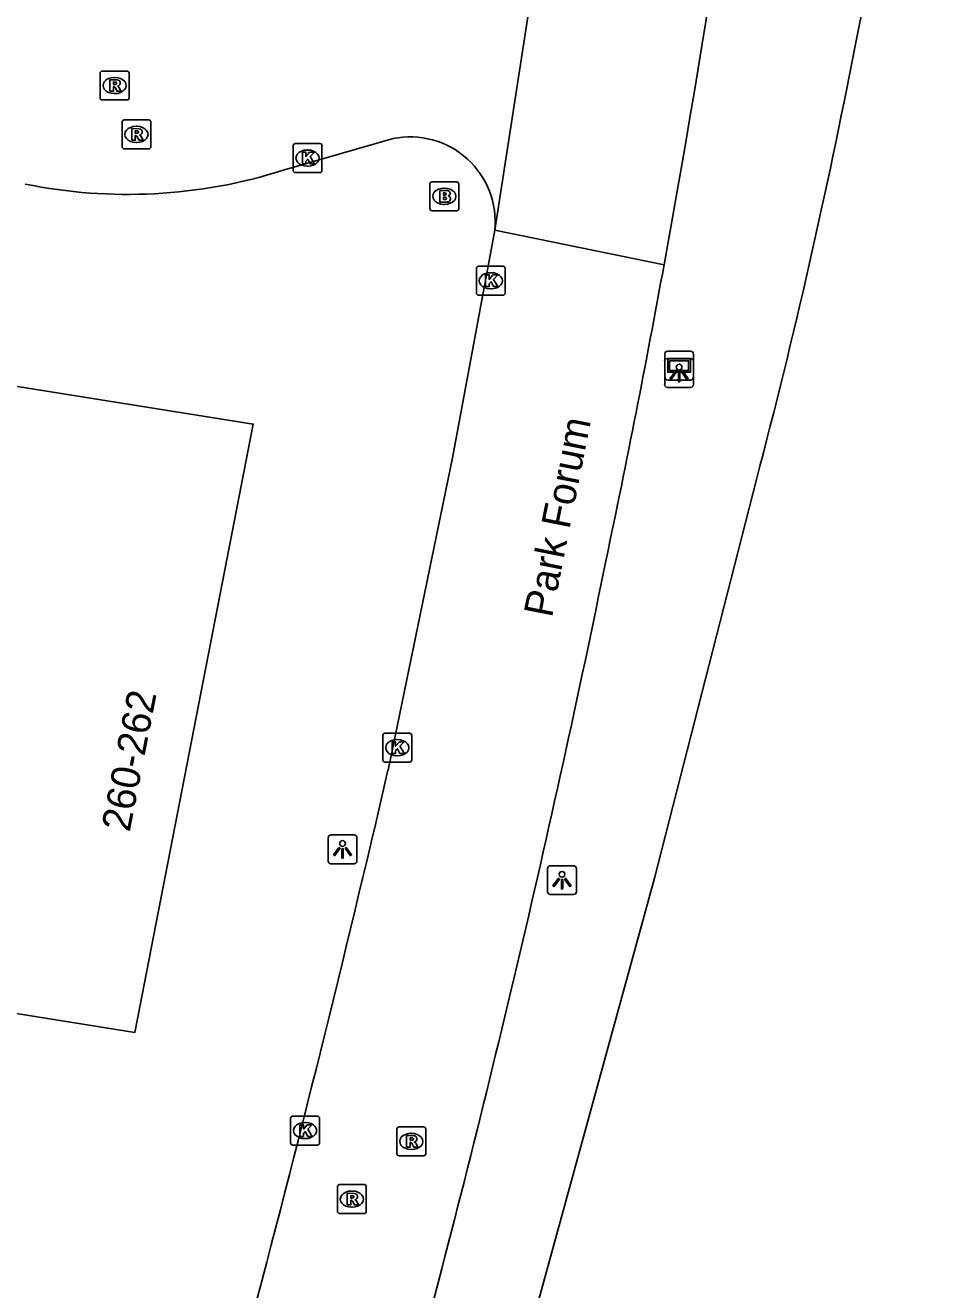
# Model space of a CAD drawing. Extents: x 154324 to 155743, y 382939 to 384183.
# Drawn here: x 155360.3 to 155392.1, y 383255.99 to 383299.76 of the extents above; entities that cross this region are included whole.
import ezdxf

# ---------------------------------------------------------------- set-up
doc = ezdxf.new("R2010")
doc.units = 0
for name, color, linetype in [('IMGEO_Brandkraan', 7, 'Continuous'), ('IMGEO_Fietspad_gesloten', 7, 'Continuous'), ('IMGEO_Kolk', 7, 'Continuous'), ('IMGEO_Lichtpunt', 7, 'Continuous'), ('IMGEO_Openbare_ruimte_label', 7, 'Continuous'), ('IMGEO_Pand', 7, 'Continuous'), ('IMGEO_Pand_nummerreeks', 7, 'Continuous'), ('IMGEO_Rijbaan_lokaal_gesloten', 7, 'Continuous'), ('IMGEO_Rijbaan_lokaal_open', 7, 'Continuous'), ('IMGEO_Rioolput', 7, 'Continuous'), ('IMGEO_Verklikker', 7, 'Continuous')]:
    doc.layers.add(name, color=color, linetype=linetype)

msp = doc.modelspace()

# ---------------------------------------------------------------- linework, layer by layer
at = {"layer": 'IMGEO_Brandkraan'}
for p, q in [((155374.307, 383293.413), (155374.307, 383294.265)), ((155374.382, 383294.339), (155375.234, 383294.339)), ((155374.795, 383294.119), (155374.82, 383294.119)), ((155375.308, 383294.265), (155375.308, 383293.413)), ((155375.234, 383293.339), (155374.382, 383293.339)), ((155374.818, 383293.559), (155374.793, 383293.559))]:
    msp.add_line(p, q, dxfattribs=at)
for points in [[(155374.307, 383293.413), (155374.307, 383294.265)], [(155374.382, 383294.339), (155375.234, 383294.339)], [(155375.308, 383294.265), (155375.308, 383293.413)], [(155374.655, 383294.039), (155374.655, 383293.639), (155374.868, 383293.639)], [(155374.886, 383294.039), (155374.655, 383294.039)], [(155374.834, 383293.958), (155374.78, 383293.958), (155374.78, 383293.882)], [(155374.78, 383293.882), (155374.833, 383293.882)], [(155374.842, 383293.806), (155374.78, 383293.806), (155374.78, 383293.725)], [(155374.78, 383293.725), (155374.842, 383293.725)], [(155375.234, 383293.339), (155374.382, 383293.339)]]:
    msp.add_lwpolyline(points, dxfattribs=at)
for centre, radius, start, end in [((155374.384, 383294.263), 0.0765, 91.552, 178.448), ((155374.384, 383294.263), 0.0765, 91.552, 178.448), ((155375.232, 383294.263), 0.0765, 1.552, 88.448), ((155375.232, 383294.263), 0.0765, 1.552, 88.448), ((155374.835, 383293.92), 0.0379, 267.8285, 90.9355), ((155374.843, 383293.765), 0.0404, 269.8759, 90.5077), ((155374.89, 383293.894), 0.145, 59.4692, 91.5367), ((155374.915, 383293.941), 0.0922, 285.5137, 58.1501), ((155374.92, 383293.749), 0.105, 301.3115, 78.989), ((155374.384, 383293.415), 0.0765, 181.552, 268.448), ((155374.384, 383293.415), 0.0765, 181.552, 268.448), ((155374.874, 383293.89), 0.251, 268.6676, 293.5347), ((155375.232, 383293.415), 0.0765, 271.552, 358.448), ((155375.232, 383293.415), 0.0765, 271.552, 358.448)]:
    msp.add_arc(centre, radius, start, end, dxfattribs=at)
for centre, major_axis, ratio, start_param, end_param in [((155374.794, 383293.839), (-0.387, 0.002), 0.722429, 4.712389, 7.853982), ((155374.819, 383293.839), (-0.39, 0.002), 0.717154, 1.570796, 4.712389)]:
    msp.add_ellipse(centre, major_axis=major_axis, ratio=ratio, start_param=start_param, end_param=end_param, dxfattribs=at)
at = {"layer": 'IMGEO_Fietspad_gesloten'}
for points in [[(155392.104, 383314.484), (155389.025, 383298.986)], [(155385.619, 383284.035), (155382.092, 383270.232), (155378.211, 383256.107)]]:
    msp.add_lwpolyline(points, dxfattribs=at)
for centre, radius, start, end in [((155162.148, 383342.808), 231.07, 345.26497, 349.06787), ((154859.102, 383401.381), 539.053, 342.73246, 344.36555)]:
    msp.add_arc(centre, radius, start, end, dxfattribs=at)
at = {"layer": 'IMGEO_Kolk'}
for p, q in [((155369.571, 383294.736), (155369.571, 383295.588)), ((155369.646, 383295.662), (155370.498, 383295.662)), ((155370.059, 383295.442), (155370.084, 383295.442)), ((155370.572, 383295.588), (155370.572, 383294.736)), ((155370.498, 383294.662), (155369.646, 383294.662)), ((155370.082, 383294.882), (155370.057, 383294.882)), ((155375.919, 383290.489), (155375.919, 383291.341)), ((155375.994, 383291.415), (155376.846, 383291.415)), ((155376.407, 383291.195), (155376.432, 383291.195)), ((155376.92, 383291.341), (155376.92, 383290.489)), ((155376.43, 383290.635), (155376.405, 383290.635)), ((155376.846, 383290.415), (155375.994, 383290.415)), ((155372.679, 383274.325), (155372.679, 383275.177)), ((155372.754, 383275.251), (155373.606, 383275.251)), ((155373.167, 383275.031), (155373.192, 383275.031)), ((155373.68, 383275.177), (155373.68, 383274.325)), ((155373.19, 383274.471), (155373.165, 383274.471)), ((155373.606, 383274.251), (155372.754, 383274.251)), ((155369.486, 383261.069), (155369.486, 383261.921)), ((155369.561, 383261.995), (155370.413, 383261.995)), ((155369.974, 383261.775), (155369.999, 383261.775)), ((155370.487, 383261.921), (155370.487, 383261.069)), ((155370.413, 383260.995), (155369.561, 383260.995)), ((155369.997, 383261.215), (155369.972, 383261.215))]:
    msp.add_line(p, q, dxfattribs=at)
for points in [[(155369.571, 383294.736), (155369.571, 383295.588)], [(155369.646, 383295.662), (155370.498, 383295.662)], [(155370.572, 383295.588), (155370.572, 383294.736)], [(155369.892, 383295.362), (155370.015, 383295.362), (155370.015, 383295.211), (155370.145, 383295.362), (155370.309, 383295.362), (155370.163, 383295.211), (155370.316, 383294.962), (155370.164, 383294.962), (155370.079, 383295.126), (155370.015, 383295.059), (155370.015, 383294.962), (155369.892, 383294.962), (155369.892, 383295.362)], [(155370.498, 383294.662), (155369.646, 383294.662)], [(155375.919, 383290.489), (155375.919, 383291.341)], [(155375.994, 383291.415), (155376.846, 383291.415)], [(155376.24, 383291.115), (155376.363, 383291.115), (155376.363, 383290.964), (155376.493, 383291.115), (155376.657, 383291.115), (155376.511, 383290.964), (155376.664, 383290.715), (155376.512, 383290.715), (155376.427, 383290.879), (155376.363, 383290.812), (155376.363, 383290.715), (155376.24, 383290.715), (155376.24, 383291.115)], [(155376.92, 383291.341), (155376.92, 383290.489)], [(155376.846, 383290.415), (155375.994, 383290.415)], [(155372.679, 383274.325), (155372.679, 383275.177)], [(155372.754, 383275.251), (155373.606, 383275.251)], [(155373, 383274.951), (155373.123, 383274.951), (155373.123, 383274.8), (155373.253, 383274.951), (155373.417, 383274.951), (155373.271, 383274.8), (155373.424, 383274.551), (155373.272, 383274.551), (155373.187, 383274.715), (155373.123, 383274.648), (155373.123, 383274.551), (155373, 383274.551), (155373, 383274.951)], [(155373.68, 383275.177), (155373.68, 383274.325)], [(155373.606, 383274.251), (155372.754, 383274.251)], [(155369.486, 383261.069), (155369.486, 383261.921)], [(155369.561, 383261.995), (155370.413, 383261.995)], [(155370.487, 383261.921), (155370.487, 383261.069)], [(155369.807, 383261.695), (155369.93, 383261.695), (155369.93, 383261.544), (155370.06, 383261.695), (155370.224, 383261.695), (155370.078, 383261.544), (155370.231, 383261.295), (155370.079, 383261.295), (155369.994, 383261.459), (155369.93, 383261.392), (155369.93, 383261.295), (155369.807, 383261.295), (155369.807, 383261.695)], [(155370.413, 383260.995), (155369.561, 383260.995)]]:
    msp.add_lwpolyline(points, dxfattribs=at)
for centre, start, end in [((155369.648, 383295.586), 91.552, 178.448), ((155369.648, 383295.586), 91.552, 178.448), ((155370.496, 383295.586), 1.552, 88.448), ((155370.496, 383295.586), 1.552, 88.448), ((155369.648, 383294.738), 181.552, 268.448), ((155369.648, 383294.738), 181.552, 268.448), ((155370.496, 383294.738), 271.552, 358.448), ((155370.496, 383294.738), 271.552, 358.448), ((155375.996, 383291.339), 91.552, 178.448), ((155375.996, 383291.339), 91.552, 178.448), ((155376.844, 383291.339), 1.552, 88.448), ((155376.844, 383291.339), 1.552, 88.448), ((155375.996, 383290.491), 181.552, 268.448), ((155375.996, 383290.491), 181.552, 268.448), ((155376.844, 383290.491), 271.552, 358.448), ((155376.844, 383290.491), 271.552, 358.448), ((155372.756, 383275.175), 91.552, 178.448), ((155372.756, 383275.175), 91.552, 178.448), ((155373.604, 383275.175), 1.552, 88.448), ((155373.604, 383275.175), 1.552, 88.448), ((155372.756, 383274.327), 181.552, 268.448), ((155372.756, 383274.327), 181.552, 268.448), ((155373.604, 383274.327), 271.552, 358.448), ((155373.604, 383274.327), 271.552, 358.448), ((155369.563, 383261.919), 91.552, 178.448), ((155369.563, 383261.919), 91.552, 178.448), ((155370.411, 383261.919), 1.552, 88.448), ((155370.411, 383261.919), 1.552, 88.448), ((155369.563, 383261.071), 181.552, 268.448), ((155369.563, 383261.071), 181.552, 268.448), ((155370.411, 383261.071), 271.552, 358.448), ((155370.411, 383261.071), 271.552, 358.448)]:
    msp.add_arc(centre, 0.0765, start, end, dxfattribs=at)
for centre, major_axis, ratio, start_param, end_param in [((155370.058, 383295.162), (-0.387, 0.002), 0.722429, 4.712389, 7.853982), ((155370.083, 383295.162), (-0.39, 0.002), 0.717154, 1.570796, 4.712389), ((155376.406, 383290.915), (-0.387, 0.002), 0.722429, 4.712389, 7.853982), ((155376.431, 383290.915), (-0.39, 0.002), 0.717154, 1.570796, 4.712389), ((155373.166, 383274.751), (-0.387, 0.002), 0.722429, 4.712389, 7.853982), ((155373.191, 383274.751), (-0.39, 0.002), 0.717154, 1.570796, 4.712389), ((155369.973, 383261.495), (-0.387, 0.002), 0.722429, 4.712389, 7.853982), ((155369.998, 383261.495), (-0.39, 0.002), 0.717154, 1.570796, 4.712389)]:
    msp.add_ellipse(centre, major_axis=major_axis, ratio=ratio, start_param=start_param, end_param=end_param, dxfattribs=at)
at = {"layer": 'IMGEO_Lichtpunt'}
for p, q in [((155382.44, 383288.126), (155382.44, 383287.319)), ((155382.44, 383288.126), (155382.44, 383287.319)), ((155383.342, 383288.221), (155382.534, 383288.221)), ((155383.342, 383288.221), (155382.534, 383288.221)), ((155383.436, 383287.319), (155383.436, 383288.126)), ((155383.436, 383287.319), (155383.436, 383288.126)), ((155382.534, 383287.225), (155383.342, 383287.225)), ((155382.534, 383287.225), (155383.342, 383287.225)), ((155370.785, 383271.634), (155370.785, 383270.827)), ((155370.785, 383271.634), (155370.785, 383270.827)), ((155371.687, 383271.729), (155370.879, 383271.729)), ((155371.687, 383271.729), (155370.879, 383271.729)), ((155371.781, 383270.827), (155371.781, 383271.634)), ((155371.781, 383270.827), (155371.781, 383271.634)), ((155370.879, 383270.733), (155371.687, 383270.733)), ((155370.879, 383270.733), (155371.687, 383270.733)), ((155378.385, 383270.568), (155378.385, 383269.761)), ((155378.385, 383270.568), (155378.385, 383269.761)), ((155379.287, 383270.663), (155378.479, 383270.663)), ((155379.287, 383270.663), (155378.479, 383270.663)), ((155379.381, 383269.761), (155379.381, 383270.568)), ((155379.381, 383269.761), (155379.381, 383270.568)), ((155378.479, 383269.667), (155379.287, 383269.667)), ((155378.479, 383269.667), (155379.287, 383269.667))]:
    msp.add_line(p, q, dxfattribs=at)
for points in [[(155382.814, 383287.79), (155382.853, 383287.762), (155382.665, 383287.5), (155382.627, 383287.527), (155382.814, 383287.79)], [(155382.916, 383287.742), (155382.963, 383287.742), (155382.963, 383287.42), (155382.916, 383287.42), (155382.916, 383287.742)], [(155383.026, 383287.762), (155383.064, 383287.789), (155383.251, 383287.527), (155383.212, 383287.499), (155383.026, 383287.762)], [(155371.159, 383271.298), (155371.198, 383271.27), (155371.01, 383271.008), (155370.972, 383271.035), (155371.159, 383271.298)], [(155371.261, 383271.25), (155371.308, 383271.25), (155371.308, 383270.928), (155371.261, 383270.928), (155371.261, 383271.25)], [(155371.371, 383271.27), (155371.409, 383271.297), (155371.596, 383271.035), (155371.557, 383271.007), (155371.371, 383271.27)], [(155378.759, 383270.232), (155378.798, 383270.204), (155378.61, 383269.942), (155378.572, 383269.969), (155378.759, 383270.232)], [(155378.861, 383270.184), (155378.908, 383270.184), (155378.908, 383269.862), (155378.861, 383269.862), (155378.861, 383270.184)], [(155378.971, 383270.204), (155379.009, 383270.231), (155379.196, 383269.969), (155379.157, 383269.941), (155378.971, 383270.204)]]:
    msp.add_lwpolyline(points, dxfattribs=at)
for centre in [(155382.939, 383287.924), (155371.284, 383271.432), (155378.884, 383270.366)]:
    msp.add_circle(centre, 0.0994, dxfattribs=at)
for centre, start, end in [((155382.534, 383288.126), 90, 180), ((155382.534, 383288.126), 90, 180), ((155383.342, 383288.126), 0, 90), ((155383.342, 383288.126), 0, 90), ((155382.534, 383287.319), 180, 270), ((155382.534, 383287.319), 180, 270), ((155383.342, 383287.319), 270, 0), ((155383.342, 383287.319), 270, 360), ((155370.879, 383271.634), 90, 180), ((155370.879, 383271.634), 90, 180), ((155371.687, 383271.634), 0, 90), ((155371.687, 383271.634), 0, 90), ((155370.879, 383270.827), 180, 270), ((155370.879, 383270.827), 180, 270), ((155371.687, 383270.827), 270, 0), ((155371.687, 383270.827), 270, 360), ((155378.479, 383270.568), 90, 180), ((155378.479, 383270.568), 90, 180), ((155379.287, 383270.568), 0, 90), ((155379.287, 383270.568), 0, 90), ((155378.479, 383269.761), 180, 270), ((155378.479, 383269.761), 180, 270), ((155379.287, 383269.761), 270, 0), ((155379.287, 383269.761), 270, 360)]:
    msp.add_arc(centre, 0.0946, start, end, dxfattribs=at)
at = {"layer": 'IMGEO_Pand'}
msp.add_lwpolyline([(155345.718, 383267.835), (155349.104, 383288.993), (155368.192, 383285.952), (155364.094, 383264.892), (155345.718, 383267.835)], dxfattribs=at)
at = {"layer": 'IMGEO_Rijbaan_lokaal_gesloten'}
for points in [[(155376.559, 383292.665), (155375.091, 383284.785), (155372.858, 383273.968)], [(155382.418, 383291.467), (155376.559, 383292.665)]]:
    msp.add_lwpolyline(points, dxfattribs=at)
for centre, radius, start, end in [((155004.637, 383360.399), 384.018, 348.10768, 349.65929), ((154920.161, 383375.05), 469.711, 344.96734, 348.48239), ((154771.317, 383413.289), 617.464, 345.099417, 346.959795)]:
    msp.add_arc(centre, radius, start, end, dxfattribs=at)
at = {"layer": 'IMGEO_Rijbaan_lokaal_open'}
for points in [[(155376.559, 383292.665), (155379.78, 383313.49)], [(155369.195, 383294.73), (155373.032, 383295.835)]]:
    msp.add_lwpolyline(points, dxfattribs=at)
for centre, radius, start, end in [((155001.57, 383361.032), 387.149, 349.64863, 353.73096), ((155373.627, 383292.95), 2.946, 354.4495, 101.6533), ((155363.845, 383311.656), 17.752, 258.4676, 287.5404)]:
    msp.add_arc(centre, radius, start, end, dxfattribs=at)
at = {"layer": 'IMGEO_Rioolput'}
for p, q in [((155362.888, 383297.247), (155362.888, 383298.099)), ((155362.963, 383298.173), (155363.815, 383298.173)), ((155363.889, 383298.099), (155363.889, 383297.247)), ((155363.376, 383297.953), (155363.401, 383297.953)), ((155363.399, 383297.393), (155363.374, 383297.393)), ((155363.815, 383297.173), (155362.963, 383297.173)), ((155363.646, 383295.556), (155363.646, 383296.408)), ((155363.721, 383296.482), (155364.573, 383296.482)), ((155364.647, 383296.408), (155364.647, 383295.556)), ((155364.134, 383296.262), (155364.159, 383296.262)), ((155364.573, 383295.482), (155363.721, 383295.482)), ((155364.157, 383295.702), (155364.132, 383295.702)), ((155373.164, 383260.695), (155373.164, 383261.547)), ((155373.239, 383261.621), (155374.091, 383261.621)), ((155373.652, 383261.401), (155373.677, 383261.401)), ((155374.165, 383261.547), (155374.165, 383260.695)), ((155374.091, 383260.621), (155373.239, 383260.621)), ((155373.675, 383260.841), (155373.65, 383260.841)), ((155371.106, 383258.696), (155371.106, 383259.548)), ((155371.181, 383259.622), (155372.033, 383259.622)), ((155372.107, 383259.548), (155372.107, 383258.696)), ((155371.594, 383259.402), (155371.619, 383259.402)), ((155371.617, 383258.842), (155371.592, 383258.842)), ((155372.033, 383258.622), (155371.181, 383258.622))]:
    msp.add_line(p, q, dxfattribs=at)
for points in [[(155362.888, 383297.247), (155362.888, 383298.099)], [(155362.963, 383298.173), (155363.815, 383298.173)], [(155363.889, 383298.099), (155363.889, 383297.247)], [(155363.477, 383297.871), (155363.225, 383297.873), (155363.225, 383297.473)], [(155363.225, 383297.473), (155363.349, 383297.473), (155363.349, 383297.635), (155363.36, 383297.635)], [(155363.403, 383297.792), (155363.349, 383297.792), (155363.349, 383297.711)], [(155363.349, 383297.711), (155363.401, 383297.711)], [(155363.407, 383297.606), (155363.478, 383297.473), (155363.618, 383297.473), (155363.553, 383297.599)], [(155363.815, 383297.173), (155362.963, 383297.173)], [(155363.646, 383295.556), (155363.646, 383296.408)], [(155363.721, 383296.482), (155364.573, 383296.482)], [(155364.647, 383296.408), (155364.647, 383295.556)], [(155364.235, 383296.18), (155363.983, 383296.182), (155363.983, 383295.782)], [(155363.983, 383295.782), (155364.107, 383295.782), (155364.107, 383295.944), (155364.118, 383295.944)], [(155364.161, 383296.101), (155364.107, 383296.101), (155364.107, 383296.02)], [(155364.107, 383296.02), (155364.159, 383296.02)], [(155364.165, 383295.915), (155364.236, 383295.782), (155364.376, 383295.782), (155364.311, 383295.908)], [(155364.573, 383295.482), (155363.721, 383295.482)], [(155373.164, 383260.695), (155373.164, 383261.547)], [(155373.239, 383261.621), (155374.091, 383261.621)], [(155373.753, 383261.319), (155373.501, 383261.321), (155373.501, 383260.921)], [(155374.165, 383261.547), (155374.165, 383260.695)], [(155373.501, 383260.921), (155373.625, 383260.921), (155373.625, 383261.083), (155373.636, 383261.083)], [(155373.679, 383261.24), (155373.625, 383261.24), (155373.625, 383261.159)], [(155373.625, 383261.159), (155373.677, 383261.159)], [(155373.683, 383261.054), (155373.754, 383260.921), (155373.894, 383260.921), (155373.829, 383261.047)], [(155374.091, 383260.621), (155373.239, 383260.621)], [(155371.106, 383258.696), (155371.106, 383259.548)], [(155371.181, 383259.622), (155372.033, 383259.622)], [(155372.107, 383259.548), (155372.107, 383258.696)], [(155371.695, 383259.32), (155371.443, 383259.322), (155371.443, 383258.922)], [(155371.621, 383259.241), (155371.567, 383259.241), (155371.567, 383259.16)], [(155371.567, 383259.16), (155371.619, 383259.16)], [(155371.443, 383258.922), (155371.567, 383258.922), (155371.567, 383259.084), (155371.578, 383259.084)], [(155371.625, 383259.055), (155371.696, 383258.922), (155371.836, 383258.922), (155371.771, 383259.048)], [(155372.033, 383258.622), (155371.181, 383258.622)]]:
    msp.add_lwpolyline(points, dxfattribs=at)
for centre, radius, start, end in [((155362.965, 383298.097), 0.0765, 91.552, 178.448), ((155362.965, 383298.097), 0.0765, 91.552, 178.448), ((155363.813, 383298.097), 0.0765, 1.552, 88.448), ((155363.813, 383298.097), 0.0765, 1.552, 88.448), ((155363.359, 383297.582), 0.0533, 26.0293, 88.6989), ((155363.385, 383297.9), 0.19, 274.7715, 282.9687), ((155363.409, 383297.696), 0.0964, 77.0061, 93.1865), ((155363.423, 383297.753), 0.0378, 276.6634, 79.6772), ((155363.476, 383297.761), 0.109, 350.3612, 89.416), ((155363.474, 383297.761), 0.112, 277.5842, 350.9817), ((155363.458, 383297.546), 0.108, 29.5134, 73.7905), ((155362.965, 383297.249), 0.0765, 181.552, 268.448), ((155362.965, 383297.249), 0.0765, 181.552, 268.448), ((155363.813, 383297.249), 0.0765, 271.552, 358.448), ((155363.813, 383297.249), 0.0765, 271.552, 358.448), ((155363.723, 383296.406), 0.0765, 91.552, 178.448), ((155363.723, 383296.406), 0.0765, 91.552, 178.448), ((155364.571, 383296.406), 0.0765, 1.552, 88.448), ((155364.571, 383296.406), 0.0765, 1.552, 88.448), ((155364.117, 383295.891), 0.0533, 26.0293, 88.6989), ((155364.143, 383296.209), 0.19, 274.7715, 282.9687), ((155364.167, 383296.005), 0.0964, 77.0061, 93.1865), ((155364.181, 383296.062), 0.0378, 276.6634, 79.6772), ((155364.234, 383296.07), 0.109, 350.3612, 89.416), ((155364.232, 383296.07), 0.112, 277.5842, 350.9817), ((155364.216, 383295.855), 0.108, 29.5134, 73.7905), ((155363.723, 383295.558), 0.0765, 181.552, 268.448), ((155363.723, 383295.558), 0.0765, 181.552, 268.448), ((155364.571, 383295.558), 0.0765, 271.552, 358.448), ((155364.571, 383295.558), 0.0765, 271.552, 358.448), ((155373.241, 383261.545), 0.0765, 91.552, 178.448), ((155373.241, 383261.545), 0.0765, 91.552, 178.448), ((155373.752, 383261.209), 0.109, 350.3612, 89.416), ((155374.089, 383261.545), 0.0765, 1.552, 88.448), ((155374.089, 383261.545), 0.0765, 1.552, 88.448), ((155373.635, 383261.03), 0.0533, 26.0293, 88.6989), ((155373.661, 383261.348), 0.19, 274.7715, 282.9687), ((155373.685, 383261.144), 0.0964, 77.0061, 93.1865), ((155373.699, 383261.201), 0.0378, 276.6634, 79.6772), ((155373.75, 383261.209), 0.112, 277.5842, 350.9817), ((155373.734, 383260.994), 0.108, 29.5134, 73.7905), ((155373.241, 383260.697), 0.0765, 181.552, 268.448), ((155373.241, 383260.697), 0.0765, 181.552, 268.448), ((155374.089, 383260.697), 0.0765, 271.552, 358.448), ((155374.089, 383260.697), 0.0765, 271.552, 358.448), ((155371.183, 383259.546), 0.0765, 91.552, 178.448), ((155371.183, 383259.546), 0.0765, 91.552, 178.448), ((155372.031, 383259.546), 0.0765, 1.552, 88.448), ((155372.031, 383259.546), 0.0765, 1.552, 88.448), ((155371.603, 383259.349), 0.19, 274.7715, 282.9687), ((155371.627, 383259.145), 0.0964, 77.0061, 93.1865), ((155371.641, 383259.202), 0.0378, 276.6634, 79.6772), ((155371.694, 383259.21), 0.109, 350.3612, 89.416), ((155371.692, 383259.21), 0.112, 277.5842, 350.9817), ((155371.676, 383258.995), 0.108, 29.5134, 73.7905), ((155371.183, 383258.698), 0.0765, 181.552, 268.448), ((155371.183, 383258.698), 0.0765, 181.552, 268.448), ((155371.577, 383259.031), 0.0533, 26.0293, 88.6989), ((155372.031, 383258.698), 0.0765, 271.552, 358.448), ((155372.031, 383258.698), 0.0765, 271.552, 358.448)]:
    msp.add_arc(centre, radius, start, end, dxfattribs=at)
for centre, major_axis, ratio, start_param, end_param in [((155363.375, 383297.673), (-0.387, 0.002), 0.722429, 4.712389, 7.853982), ((155363.4, 383297.673), (-0.39, 0.002), 0.717154, 1.570796, 4.712389), ((155364.133, 383295.982), (-0.387, 0.002), 0.722429, 4.712389, 7.853982), ((155364.158, 383295.982), (-0.39, 0.002), 0.717154, 1.570796, 4.712389), ((155373.651, 383261.121), (-0.387, 0.002), 0.722429, 4.712389, 7.853982), ((155373.676, 383261.121), (-0.39, 0.002), 0.717154, 1.570796, 4.712389), ((155371.593, 383259.122), (-0.387, 0.002), 0.722429, 4.712389, 7.853982), ((155371.618, 383259.122), (-0.39, 0.002), 0.717154, 1.570796, 4.712389)]:
    msp.add_ellipse(centre, major_axis=major_axis, ratio=ratio, start_param=start_param, end_param=end_param, dxfattribs=at)
at = {"layer": 'IMGEO_Verklikker'}
for p, q in [((155382.544, 383288.479), (155383.334, 383288.479)), ((155383.334, 383288.479), (155382.544, 383288.479)), ((155382.444, 383287.579), (155382.444, 383288.379)), ((155382.444, 383288.379), (155382.444, 383287.579)), ((155383.434, 383288.379), (155383.434, 383287.579)), ((155383.434, 383287.579), (155383.434, 383288.379)), ((155383.334, 383287.479), (155382.544, 383287.479)), ((155382.544, 383287.479), (155383.334, 383287.479))]:
    msp.add_line(p, q, dxfattribs=at)
for points in [[(155382.545, 383288.211), (155383.333, 383288.211), (155383.333, 383287.747), (155382.545, 383287.747), (155382.545, 383288.211)], [(155382.61, 383288.146), (155382.61, 383287.812), (155383.268, 383287.812), (155383.268, 383288.146), (155382.61, 383288.146)]]:
    msp.add_lwpolyline(points, dxfattribs=at)
for centre, start, end in [((155382.544, 383288.379), 90, 180), ((155382.544, 383288.379), 90, 180), ((155383.334, 383288.379), 0, 90), ((155383.334, 383288.379), 360, 90), ((155382.544, 383287.579), 180, 270), ((155382.544, 383287.579), 180, 270), ((155383.334, 383287.579), 270, 0), ((155383.334, 383287.579), 270, 0)]:
    msp.add_arc(centre, 0.1, start, end, dxfattribs=at)

# ---------------------------------------------------------------- texts
at = {"layer": 'IMGEO_Openbare_ruimte_label'}
msp.add_text('Park Forum', height=1, rotation=78.8137, dxfattribs=at).set_placement((155378.534, 383279.224))
at = {"layer": 'IMGEO_Pand_nummerreeks'}
msp.add_text('260-262', height=1, rotation=78.988, dxfattribs=at).set_placement((155363.911, 383271.804))

doc.saveas('drawing.dxf')
